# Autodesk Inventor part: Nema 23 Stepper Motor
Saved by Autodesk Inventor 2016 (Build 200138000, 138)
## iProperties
Created: 2015-11
Part Number: Nema 23 Stepper Motor
Material: Generic
Document SubType Name: Modeling
Designer: John
Density: 1 g/cm^3
Appearance: Default
Author: John
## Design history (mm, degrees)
feature "SOLID1"
body "Solid1"
